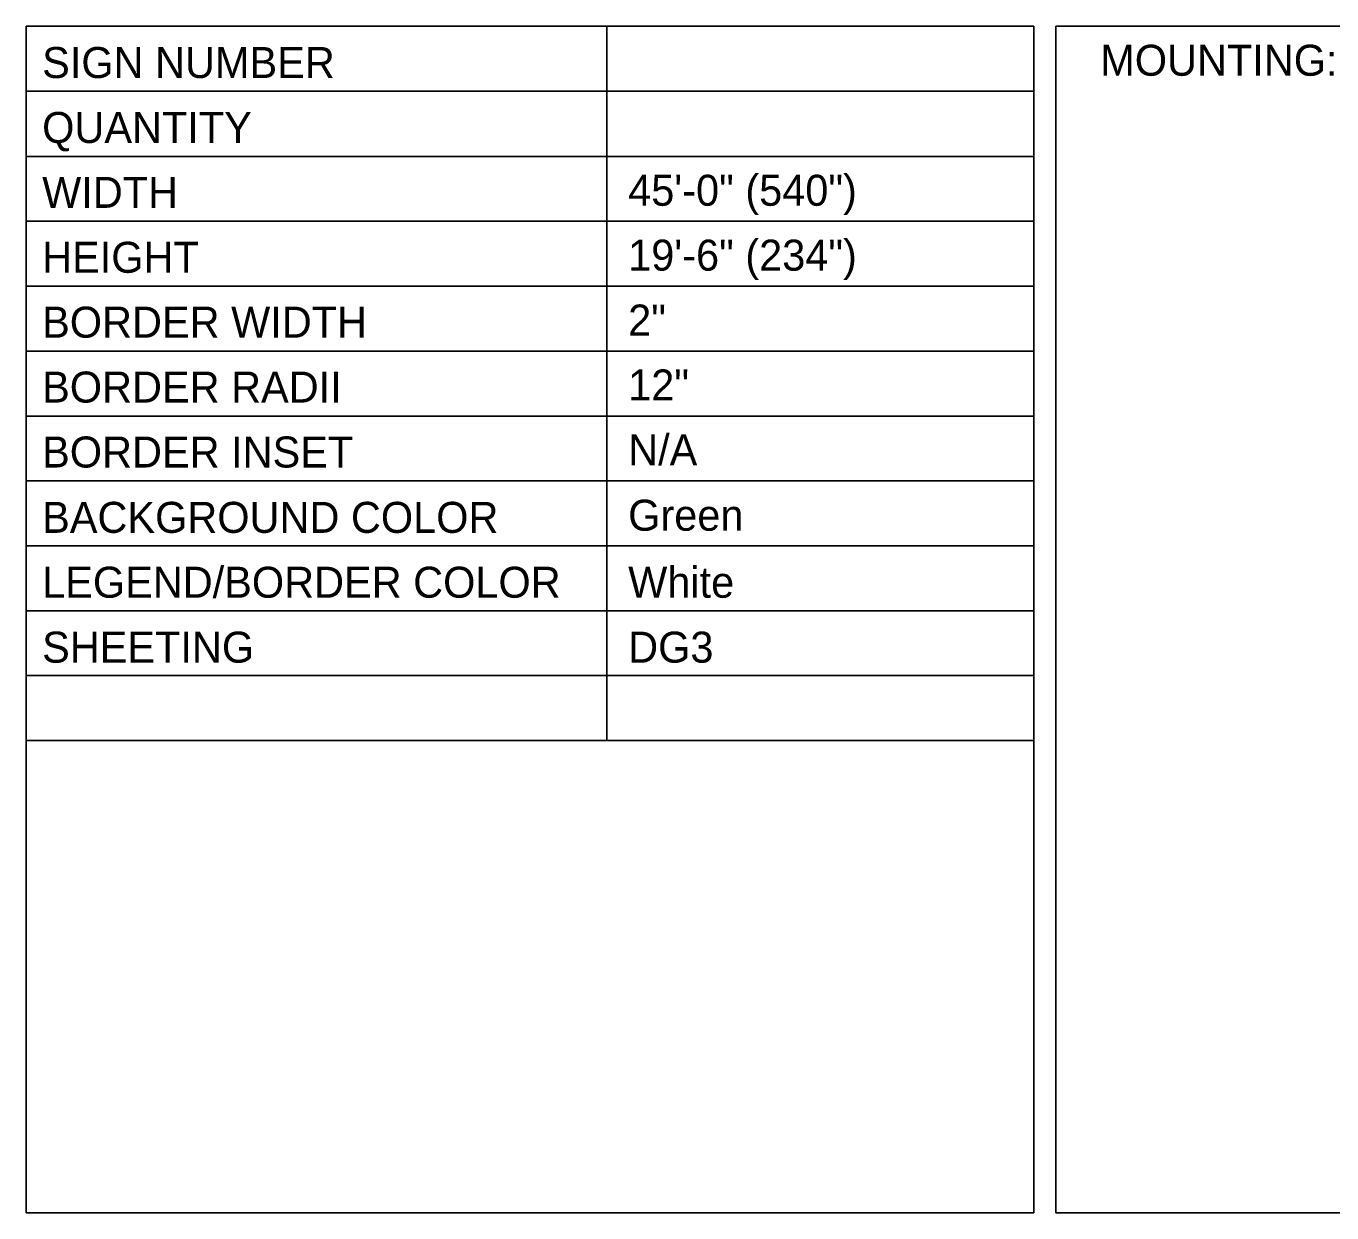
# Model space of a CAD drawing. Extents: x 531799 to 532094, y 1531149 to 1533620.
# Drawn here: x 531804.41 to 531829.46, y 1531174.3 to 1531197.08 of the extents above; entities that cross this region are included whole.
import ezdxf

# ---------------------------------------------------------------- set-up
doc = ezdxf.new("R2010")
doc.units = 0
for name, color, linetype in [('SumBoxLines_dp', 7, 'Continuous'), ('TextLabel', 7, 'Continuous'), ('TextMisc', 7, 'Continuous')]:
    doc.layers.add(name, color=color, linetype=linetype)

msp = doc.modelspace()

# ---------------------------------------------------------------- linework, layer by layer
at = {"layer": 'SumBoxLines_dp'}
for p, q in [((531804.413, 1531197.077), (531804.413, 1531174.302)), ((531804.413, 1531197.077), (531823.746, 1531197.077)), ((531815.556, 1531197.073), (531815.556, 1531183.366)), ((531823.746, 1531197.077), (531823.746, 1531174.302)), ((531824.171, 1531197.077), (531824.171, 1531174.302)), ((531824.171, 1531197.077), (531878.771, 1531197.077)), ((531804.413, 1531195.831), (531823.746, 1531195.831)), ((531804.413, 1531194.577), (531823.746, 1531194.577)), ((531804.413, 1531193.331), (531823.746, 1531193.331)), ((531804.413, 1531192.086), (531823.746, 1531192.086)), ((531804.413, 1531190.84), (531823.746, 1531190.84)), ((531804.413, 1531189.594), (531823.746, 1531189.594)), ((531804.413, 1531188.349), (531823.746, 1531188.349)), ((531804.413, 1531187.103), (531823.746, 1531187.103)), ((531804.413, 1531185.858), (531823.746, 1531185.858)), ((531804.413, 1531184.612), (531823.746, 1531184.612)), ((531804.413, 1531183.366), (531823.746, 1531183.366)), ((531804.413, 1531174.302), (531823.746, 1531174.302)), ((531824.171, 1531174.302), (531878.771, 1531174.302))]:
    msp.add_line(p, q, dxfattribs=at)

# ---------------------------------------------------------------- texts
at = {"layer": 'TextLabel'}
for s, p in [('MOUNTING: OVERHEAD TRUSS ', (531825.021, 1531196.124)), ('45\'-0" (540")', (531815.964, 1531193.629)), ('19\'-6" (234")', (531815.964, 1531192.384)), ('2"', (531815.964, 1531191.138)), ('12"', (531815.964, 1531189.892)), ('N/A', (531815.964, 1531188.647)), ('Green', (531815.964, 1531187.393)), ('White', (531815.964, 1531186.107)), ('DG3', (531815.964, 1531184.861))]:
    msp.add_text(s, height=0.595, dxfattribs=at).set_placement(p)
at = {"layer": 'TextMisc'}
for s, p in [('SIGN NUMBER', (531804.721, 1531196.08)), ('QUANTITY', (531804.721, 1531194.834)), ('WIDTH', (531804.721, 1531193.589)), ('HEIGHT', (531804.721, 1531192.343)), ('BORDER WIDTH', (531804.721, 1531191.098)), ('BORDER RADII', (531804.721, 1531189.852)), ('BORDER INSET', (531804.721, 1531188.606)), ('BACKGROUND COLOR', (531804.721, 1531187.352)), ('LEGEND/BORDER COLOR', (531804.721, 1531186.107)), ('SHEETING', (531804.721, 1531184.861))]:
    msp.add_text(s, height=0.595, dxfattribs=at).set_placement(p)

doc.saveas('drawing.dxf')
